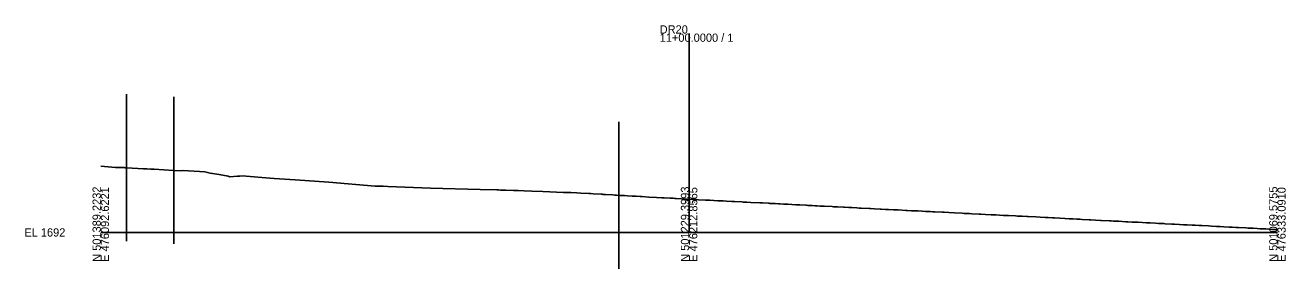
# Model space of a CAD drawing. Extents: x 78027 to 79855, y -93601 to -93005.
# Drawn here: x 79426.8 to 79855.3, y -93589.6 to -93506.7 of the extents above; entities that cross this region are included whole.
import ezdxf

# ---------------------------------------------------------------- set-up
doc = ezdxf.new("R2010")
doc.units = 0
for name, color, linetype in [('Exist Cross Section Cell', 7, 'Continuous'), ('Exist XS Center Line Elevation Label', 7, 'Continuous'), ('Exist XS Ground Line', 7, 'Continuous'), ('Scratch_Level_0', 7, 'Continuous'), ('Scratch_Level_4', 7, 'Continuous'), ('Scratch_Level_5', 7, 'Continuous'), ('Scratch_Level_6', 7, 'Continuous')]:
    doc.layers.add(name, color=color, linetype=linetype)

msp = doc.modelspace()

# ---------------------------------------------------------------- linework, layer by layer
at = {"layer": 'Exist Cross Section Cell'}
for p, q in [((79652.48, -93577.22), (79652.48, -93509.58)), ((79452.48, -93577.22), (79652.48, -93577.22)), ((79652.48, -93577.22), (79852.48, -93577.22))]:
    msp.add_line(p, q, dxfattribs=at)
at = {"layer": 'Exist XS Ground Line'}
msp.add_lwpolyline([(79452.48, -93554.67), (79457.47, -93555.08), (79460.4, -93555.15), (79460.76, -93555.21), (79461.28, -93555.22), (79467, -93555.55), (79468.19, -93555.63), (79469.48, -93555.68), (79470.02, -93555.72), (79470.61, -93555.75), (79477.17, -93556.1), (79479.76, -93556.22), (79480.44, -93556.1), (79487.87, -93556.64), (79489.7, -93557.09), (79492.77, -93557.53), (79495.73, -93558.11), (79496.34, -93558.31), (79498.98, -93558.05), (79499.78, -93558.04), (79501.14, -93557.95), (79501.94, -93558.03), (79509.9, -93558.78), (79511.48, -93558.86), (79518.6, -93559.3), (79529.97, -93560.16), (79545.75, -93561.44), (79548.53, -93561.53), (79550.05, -93561.58), (79564.52, -93562.17), (79581.42, -93562.59), (79587.13, -93562.76), (79587.66, -93562.78), (79588.31, -93562.8), (79589.12, -93562.83), (79590.17, -93562.87), (79592.84, -93562.95), (79594.39, -93563.01), (79596.38, -93563.08), (79599.04, -93563.18), (79602.73, -93563.32), (79609.81, -93563.6), (79612.26, -93563.68), (79614.26, -93563.75), (79615.69, -93563.84), (79618.45, -93563.99), (79619.04, -93564.03), (79619.83, -93564.08), (79622.62, -93564.24), (79622.97, -93564.26), (79623.32, -93564.28), (79624.05, -93564.32), (79626.58, -93564.47), (79627.26, -93564.51), (79627.77, -93564.54), (79629.1, -93564.62), (79630.56, -93564.7), (79631.54, -93564.76), (79633.07, -93564.84), (79633.66, -93564.89), (79634.53, -93564.93), (79635.89, -93565), (79636.36, -93565.03), (79638.81, -93565.17), (79641.37, -93565.31), (79643.26, -93565.41), (79643.67, -93565.43), (79644, -93565.45), (79646.07, -93565.57), (79647.07, -93565.62), (79647.63, -93565.65), (79648.07, -93565.67), (79649.93, -93565.77), (79651.59, -93565.86), (79652.73, -93565.92), (79654.23, -93566), (79655.02, -93566.04), (79655.65, -93566.08), (79658.06, -93566.2), (79659.17, -93566.26), (79659.54, -93566.28), (79660.86, -93566.35), (79662.27, -93566.42), (79664.01, -93566.51), (79665.22, -93566.57), (79666.98, -93566.66), (79667.48, -93566.69), (79667.9, -93566.71), (79670.35, -93566.84), (79670.88, -93566.87), (79672.05, -93566.93), (79673.43, -93567), (79676.48, -93567.16), (79677.41, -93567.2), (79679.64, -93567.32), (79679.97, -93567.34), (79680.31, -93567.35), (79681.79, -93567.43), (79682.84, -93567.48), (79683.35, -93567.51), (79684.54, -93567.57), (79685.36, -93567.62), (79686, -93567.65), (79688.71, -93567.79), (79689.06, -93567.81), (79690.11, -93567.87), (79692.14, -93567.97), (79692.44, -93567.99), (79692.81, -93568.01), (79694.27, -93568.08), (79695.31, -93568.14), (79696.03, -93568.18), (79697, -93568.23), (79697.85, -93568.27), (79698.5, -93568.31), (79701.15, -93568.45), (79701.6, -93568.47), (79702.88, -93568.54), (79704.93, -93568.64), (79705.29, -93568.66), (79706.77, -93568.74), (79707.81, -93568.79), (79709.48, -93568.88), (79710.35, -93568.92), (79711.02, -93568.96), (79713.64, -93569.09), (79714.11, -93569.12), (79715.47, -93569.19), (79717.42, -93569.28), (79717.76, -93569.3), (79719.25, -93569.38), (79720.32, -93569.43), (79721.97, -93569.51), (79722.86, -93569.56), (79723.52, -93569.59), (79726.11, -93569.72), (79726.64, -93569.75), (79728.1, -93569.82), (79729.92, -93569.91), (79730.24, -93569.93), (79731.74, -93570.01), (79732.83, -93570.06), (79733.51, -93570.09), (79734.44, -93570.14), (79735.36, -93570.19), (79736.06, -93570.22), (79738.59, -93570.35), (79739.15, -93570.38), (79740.73, -93570.46), (79742.71, -93570.56), (79745.36, -93570.69), (79746.02, -93570.73), (79746.9, -93570.77), (79747.84, -93570.82), (79748.58, -93570.86), (79751.07, -93570.98), (79751.61, -93571), (79753.28, -93571.09), (79755.18, -93571.19), (79756.76, -93571.27), (79757.96, -93571.33), (79759.4, -93571.41), (79761.03, -93571.49), (79763.47, -93571.61), (79764.08, -93571.64), (79765.67, -93571.73), (79767.34, -93571.81), (79767.75, -93571.83), (79770.4, -93571.97), (79771.82, -93572.04), (79773.47, -93572.13), (79774.57, -93572.19), (79776.04, -93572.26), (79776.73, -93572.3), (79778.54, -93572.39), (79780.17, -93572.48), (79781.73, -93572.56), (79782.91, -93572.62), (79784.33, -93572.69), (79785.32, -93572.74), (79786.09, -93572.78), (79788.43, -93572.9), (79789.1, -93572.94), (79790.65, -93573.03), (79792.37, -93573.11), (79792.68, -93573.13), (79795.36, -93573.27), (79795.99, -93573.3), (79796.81, -93573.35), (79797.82, -93573.4), (79798.59, -93573.44), (79800.96, -93573.56), (79801.67, -93573.6), (79803.13, -93573.68), (79805.11, -93573.77), (79807.98, -93573.93), (79809.24, -93573.99), (79811.01, -93574.08), (79812.07, -93574.14), (79813.42, -93574.21), (79813.91, -93574.23), (79814.27, -93574.25), (79816.56, -93574.37), (79817.53, -93574.42), (79819.24, -93574.51), (79820.52, -93574.58), (79821.76, -93574.64), (79823.52, -93574.73), (79824.56, -93574.79), (79825.93, -93574.86), (79826.41, -93574.88), (79826.78, -93574.9), (79829.06, -93575.02), (79830.04, -93575.07), (79831.73, -93575.16), (79833.03, -93575.23), (79834.24, -93575.29), (79836.03, -93575.39), (79837.05, -93575.44), (79838.39, -93575.51), (79838.91, -93575.54), (79839.3, -93575.56), (79841.75, -93575.69), (79842.48, -93575.73), (79844.24, -93575.82), (79845.55, -93575.89), (79846.67, -93575.95), (79848.56, -93576.05), (79849.57, -93576.1), (79850.84, -93576.17), (79851.78, -93576.22), (79852.48, -93576.26)], dxfattribs=at)
at = {"layer": 'Scratch_Level_0'}
msp.add_lwpolyline([(79452.48, -93554.67), (79457.47, -93555.08), (79460.4, -93555.15), (79460.76, -93555.21), (79461.28, -93555.22), (79467, -93555.55), (79468.19, -93555.63), (79469.48, -93555.68), (79470.02, -93555.72), (79470.61, -93555.75), (79477.17, -93556.1), (79479.76, -93556.22), (79480.44, -93556.1), (79487.87, -93556.64), (79489.7, -93557.09), (79492.77, -93557.53), (79495.73, -93558.11), (79496.34, -93558.31), (79498.98, -93558.05), (79499.78, -93558.04), (79501.14, -93557.95), (79501.94, -93558.03), (79509.9, -93558.78), (79511.48, -93558.86), (79518.6, -93559.3), (79529.97, -93560.16), (79545.75, -93561.44), (79548.53, -93561.53), (79550.05, -93561.58), (79564.52, -93562.17), (79581.42, -93562.59), (79587.13, -93562.76), (79587.66, -93562.78), (79588.31, -93562.8), (79589.12, -93562.83), (79590.17, -93562.87), (79592.84, -93562.95), (79594.39, -93563.01), (79596.38, -93563.08), (79599.04, -93563.18), (79602.73, -93563.32), (79609.81, -93563.6), (79612.26, -93563.68), (79614.26, -93563.75), (79615.69, -93563.84), (79618.45, -93563.99), (79619.04, -93564.03), (79619.83, -93564.08), (79622.62, -93564.24), (79622.97, -93564.26), (79623.32, -93564.28), (79624.05, -93564.32), (79626.58, -93564.47), (79627.26, -93564.51), (79627.77, -93564.54), (79629.1, -93564.62), (79630.56, -93564.7), (79631.54, -93564.76), (79633.07, -93564.84), (79633.66, -93564.89), (79634.53, -93564.93), (79635.89, -93565), (79636.36, -93565.03), (79638.81, -93565.17), (79641.37, -93565.31), (79643.26, -93565.41), (79643.67, -93565.43), (79644, -93565.45), (79646.07, -93565.57), (79647.07, -93565.62), (79647.63, -93565.65), (79648.07, -93565.67), (79649.93, -93565.77), (79651.59, -93565.86), (79652.73, -93565.92), (79654.23, -93566), (79655.02, -93566.04), (79655.65, -93566.08), (79658.06, -93566.2), (79659.17, -93566.26), (79659.54, -93566.28), (79660.86, -93566.35), (79662.27, -93566.42), (79664.01, -93566.51), (79665.22, -93566.57), (79666.98, -93566.66), (79667.48, -93566.69), (79667.9, -93566.71), (79670.35, -93566.84), (79670.88, -93566.87), (79672.05, -93566.93), (79673.43, -93567), (79676.48, -93567.16), (79677.41, -93567.2), (79679.64, -93567.32), (79679.97, -93567.34), (79680.31, -93567.35), (79681.79, -93567.43), (79682.84, -93567.48), (79683.35, -93567.51), (79684.54, -93567.57), (79685.36, -93567.62), (79686, -93567.65), (79688.71, -93567.79), (79689.06, -93567.81), (79690.11, -93567.87), (79692.14, -93567.97), (79692.44, -93567.99), (79692.81, -93568.01), (79694.27, -93568.08), (79695.31, -93568.14), (79696.03, -93568.18), (79697, -93568.23), (79697.85, -93568.27), (79698.5, -93568.31), (79701.15, -93568.45), (79701.6, -93568.47), (79702.88, -93568.54), (79704.93, -93568.64), (79705.29, -93568.66), (79706.77, -93568.74), (79707.81, -93568.79), (79709.48, -93568.88), (79710.35, -93568.92), (79711.02, -93568.96), (79713.64, -93569.09), (79714.11, -93569.12), (79715.47, -93569.19), (79717.42, -93569.28), (79717.76, -93569.3), (79719.25, -93569.38), (79720.32, -93569.43), (79721.97, -93569.51), (79722.86, -93569.56), (79723.52, -93569.59), (79726.11, -93569.72), (79726.64, -93569.75), (79728.1, -93569.82), (79729.92, -93569.91), (79730.24, -93569.93), (79731.74, -93570.01), (79732.83, -93570.06), (79733.51, -93570.09), (79734.44, -93570.14), (79735.36, -93570.19), (79736.06, -93570.22), (79738.59, -93570.35), (79739.15, -93570.38), (79740.73, -93570.46), (79742.71, -93570.56), (79745.36, -93570.69), (79746.02, -93570.73), (79746.9, -93570.77), (79747.84, -93570.82), (79748.58, -93570.86), (79751.07, -93570.98), (79751.61, -93571), (79753.28, -93571.09), (79755.18, -93571.19), (79756.76, -93571.27), (79757.96, -93571.33), (79759.4, -93571.41), (79761.03, -93571.49), (79763.47, -93571.61), (79764.08, -93571.64), (79765.67, -93571.73), (79767.34, -93571.81), (79767.75, -93571.83), (79770.4, -93571.97), (79771.82, -93572.04), (79773.47, -93572.13), (79774.57, -93572.19), (79776.04, -93572.26), (79776.73, -93572.3), (79778.54, -93572.39), (79780.17, -93572.48), (79781.73, -93572.56), (79782.91, -93572.62), (79784.33, -93572.69), (79785.32, -93572.74), (79786.09, -93572.78), (79788.43, -93572.9), (79789.1, -93572.94), (79790.65, -93573.03), (79792.37, -93573.11), (79792.68, -93573.13), (79795.36, -93573.27), (79795.99, -93573.3), (79796.81, -93573.35), (79797.82, -93573.4), (79798.59, -93573.44), (79800.96, -93573.56), (79801.67, -93573.6), (79803.13, -93573.68), (79805.11, -93573.77), (79807.98, -93573.93), (79809.24, -93573.99), (79811.01, -93574.08), (79812.07, -93574.14), (79813.42, -93574.21), (79813.91, -93574.23), (79814.27, -93574.25), (79816.56, -93574.37), (79817.53, -93574.42), (79819.24, -93574.51), (79820.52, -93574.58), (79821.76, -93574.64), (79823.52, -93574.73), (79824.56, -93574.79), (79825.93, -93574.86), (79826.41, -93574.88), (79826.78, -93574.9), (79829.06, -93575.02), (79830.04, -93575.07), (79831.73, -93575.16), (79833.03, -93575.23), (79834.24, -93575.29), (79836.03, -93575.39), (79837.05, -93575.44), (79838.39, -93575.51), (79838.91, -93575.54), (79839.3, -93575.56), (79841.75, -93575.69), (79842.48, -93575.73), (79844.24, -93575.82), (79845.55, -93575.89), (79846.67, -93575.95), (79848.56, -93576.05), (79849.57, -93576.1), (79850.84, -93576.17), (79851.78, -93576.22), (79852.48, -93576.26)], dxfattribs=at)
at = {"layer": 'Scratch_Level_4'}
for p, q in [((79461.28, -93530.22), (79461.28, -93580.22)), ((79477.29, -93531.11), (79477.29, -93581.11)), ((79628.63, -93539.59), (79628.63, -93589.59)), ((79628.63, -93539.59), (79628.63, -93589.59))]:
    msp.add_line(p, q, dxfattribs=at)
at = {"layer": 'Scratch_Level_5'}
msp.add_lwpolyline([(79452.48, -93554.67), (79457.47, -93555.08), (79460.4, -93555.15), (79460.76, -93555.21), (79461.28, -93555.22), (79467, -93555.55), (79468.19, -93555.63), (79469.48, -93555.68), (79470.02, -93555.72), (79470.61, -93555.75), (79477.17, -93556.1), (79479.76, -93556.22), (79480.44, -93556.1), (79487.87, -93556.64), (79489.7, -93557.09), (79492.77, -93557.53), (79495.73, -93558.11), (79496.34, -93558.31), (79498.98, -93558.05), (79499.78, -93558.04), (79501.14, -93557.95), (79501.94, -93558.03), (79509.9, -93558.78), (79511.48, -93558.86), (79518.6, -93559.3), (79529.97, -93560.16), (79545.75, -93561.44), (79548.53, -93561.53), (79550.05, -93561.58), (79564.52, -93562.17), (79581.42, -93562.59), (79587.13, -93562.76), (79587.66, -93562.78), (79588.31, -93562.8), (79589.12, -93562.83), (79590.17, -93562.87), (79592.84, -93562.95), (79594.39, -93563.01), (79596.38, -93563.08), (79599.04, -93563.18), (79602.73, -93563.32), (79609.81, -93563.6), (79612.26, -93563.68), (79614.26, -93563.75), (79615.69, -93563.84), (79618.45, -93563.99), (79619.04, -93564.03), (79619.83, -93564.08), (79622.62, -93564.24), (79622.97, -93564.26), (79623.32, -93564.28), (79624.05, -93564.32), (79626.58, -93564.47), (79627.26, -93564.51), (79627.77, -93564.54), (79629.1, -93564.62), (79630.56, -93564.7), (79631.54, -93564.76), (79633.07, -93564.84), (79633.66, -93564.89), (79634.53, -93564.93), (79635.89, -93565), (79636.36, -93565.03), (79638.81, -93565.17), (79641.37, -93565.31), (79643.26, -93565.41), (79643.67, -93565.43), (79644, -93565.45), (79646.07, -93565.57), (79647.07, -93565.62), (79647.63, -93565.65), (79648.07, -93565.67), (79649.93, -93565.77), (79651.59, -93565.86), (79652.73, -93565.92), (79654.23, -93566), (79655.02, -93566.04), (79655.65, -93566.08), (79658.06, -93566.2), (79659.17, -93566.26), (79659.54, -93566.28), (79660.86, -93566.35), (79662.27, -93566.42), (79664.01, -93566.51), (79665.22, -93566.57), (79666.98, -93566.66), (79667.48, -93566.69), (79667.9, -93566.71), (79670.35, -93566.84), (79670.88, -93566.87), (79672.05, -93566.93), (79673.43, -93567), (79676.48, -93567.16), (79677.41, -93567.2), (79679.64, -93567.32), (79679.97, -93567.34), (79680.31, -93567.35), (79681.79, -93567.43), (79682.84, -93567.48), (79683.35, -93567.51), (79684.54, -93567.57), (79685.36, -93567.62), (79686, -93567.65), (79688.71, -93567.79), (79689.06, -93567.81), (79690.11, -93567.87), (79692.14, -93567.97), (79692.44, -93567.99), (79692.81, -93568.01), (79694.27, -93568.08), (79695.31, -93568.14), (79696.03, -93568.18), (79697, -93568.23), (79697.85, -93568.27), (79698.5, -93568.31), (79701.15, -93568.45), (79701.6, -93568.47), (79702.88, -93568.54), (79704.93, -93568.64), (79705.29, -93568.66), (79706.77, -93568.74), (79707.81, -93568.79), (79709.48, -93568.88), (79710.35, -93568.92), (79711.02, -93568.96), (79713.64, -93569.09), (79714.11, -93569.12), (79715.47, -93569.19), (79717.42, -93569.28), (79717.76, -93569.3), (79719.25, -93569.38), (79720.32, -93569.43), (79721.97, -93569.51), (79722.86, -93569.56), (79723.52, -93569.59), (79726.11, -93569.72), (79726.64, -93569.75), (79728.1, -93569.82), (79729.92, -93569.91), (79730.24, -93569.93), (79731.74, -93570.01), (79732.83, -93570.06), (79733.51, -93570.09), (79734.44, -93570.14), (79735.36, -93570.19), (79736.06, -93570.22), (79738.59, -93570.35), (79739.15, -93570.38), (79740.73, -93570.46), (79742.71, -93570.56), (79745.36, -93570.69), (79746.02, -93570.73), (79746.9, -93570.77), (79747.84, -93570.82), (79748.58, -93570.86), (79751.07, -93570.98), (79751.61, -93571), (79753.28, -93571.09), (79755.18, -93571.19), (79756.76, -93571.27), (79757.96, -93571.33), (79759.4, -93571.41), (79761.03, -93571.49), (79763.47, -93571.61), (79764.08, -93571.64), (79765.67, -93571.73), (79767.34, -93571.81), (79767.75, -93571.83), (79770.4, -93571.97), (79771.82, -93572.04), (79773.47, -93572.13), (79774.57, -93572.19), (79776.04, -93572.26), (79776.73, -93572.3), (79778.54, -93572.39), (79780.17, -93572.48), (79781.73, -93572.56), (79782.91, -93572.62), (79784.33, -93572.69), (79785.32, -93572.74), (79786.09, -93572.78), (79788.43, -93572.9), (79789.1, -93572.94), (79790.65, -93573.03), (79792.37, -93573.11), (79792.68, -93573.13), (79795.36, -93573.27), (79795.99, -93573.3), (79796.81, -93573.35), (79797.82, -93573.4), (79798.59, -93573.44), (79800.96, -93573.56), (79801.67, -93573.6), (79803.13, -93573.68), (79805.11, -93573.77), (79807.98, -93573.93), (79809.24, -93573.99), (79811.01, -93574.08), (79812.07, -93574.14), (79813.42, -93574.21), (79813.91, -93574.23), (79814.27, -93574.25), (79816.56, -93574.37), (79817.53, -93574.42), (79819.24, -93574.51), (79820.52, -93574.58), (79821.76, -93574.64), (79823.52, -93574.73), (79824.56, -93574.79), (79825.93, -93574.86), (79826.41, -93574.88), (79826.78, -93574.9), (79829.06, -93575.02), (79830.04, -93575.07), (79831.73, -93575.16), (79833.03, -93575.23), (79834.24, -93575.29), (79836.03, -93575.39), (79837.05, -93575.44), (79838.39, -93575.51), (79838.91, -93575.54), (79839.3, -93575.56), (79841.75, -93575.69), (79842.48, -93575.73), (79844.24, -93575.82), (79845.55, -93575.89), (79846.67, -93575.95), (79848.56, -93576.05), (79849.57, -93576.1), (79850.84, -93576.17), (79851.78, -93576.22), (79852.48, -93576.26)], dxfattribs=at)
at = {"layer": 'Scratch_Level_6'}
msp.add_lwpolyline([(79452.48, -93554.67), (79457.47, -93555.08), (79460.4, -93555.15), (79460.76, -93555.21), (79461.28, -93555.22), (79467, -93555.55), (79468.19, -93555.63), (79469.48, -93555.68), (79470.02, -93555.72), (79470.61, -93555.75), (79477.17, -93556.1), (79479.76, -93556.22), (79480.44, -93556.1), (79487.87, -93556.64), (79489.7, -93557.09), (79492.77, -93557.53), (79495.73, -93558.11), (79496.34, -93558.31), (79498.98, -93558.05), (79499.78, -93558.04), (79501.14, -93557.95), (79501.94, -93558.03), (79509.9, -93558.78), (79511.48, -93558.86), (79518.6, -93559.3), (79529.97, -93560.16), (79545.75, -93561.44), (79548.53, -93561.53), (79550.05, -93561.58), (79564.52, -93562.17), (79581.42, -93562.59), (79587.13, -93562.76), (79587.66, -93562.78), (79588.31, -93562.8), (79589.12, -93562.83), (79590.17, -93562.87), (79592.84, -93562.95), (79594.39, -93563.01), (79596.38, -93563.08), (79599.04, -93563.18), (79602.73, -93563.32), (79609.81, -93563.6), (79612.26, -93563.68), (79614.26, -93563.75), (79615.69, -93563.84), (79618.45, -93563.99), (79619.04, -93564.03), (79619.83, -93564.08), (79622.62, -93564.24), (79622.97, -93564.26), (79623.32, -93564.28), (79624.05, -93564.32), (79626.58, -93564.47), (79627.26, -93564.51), (79627.77, -93564.54), (79629.1, -93564.62), (79630.56, -93564.7), (79631.54, -93564.76), (79633.07, -93564.84), (79633.66, -93564.89), (79634.53, -93564.93), (79635.89, -93565), (79636.36, -93565.03), (79638.81, -93565.17), (79641.37, -93565.31), (79643.26, -93565.41), (79643.67, -93565.43), (79644, -93565.45), (79646.07, -93565.57), (79647.07, -93565.62), (79647.63, -93565.65), (79648.07, -93565.67), (79649.93, -93565.77), (79651.59, -93565.86), (79652.73, -93565.92), (79654.23, -93566), (79655.02, -93566.04), (79655.65, -93566.08), (79658.06, -93566.2), (79659.17, -93566.26), (79659.54, -93566.28), (79660.86, -93566.35), (79662.27, -93566.42), (79664.01, -93566.51), (79665.22, -93566.57), (79666.98, -93566.66), (79667.48, -93566.69), (79667.9, -93566.71), (79670.35, -93566.84), (79670.88, -93566.87), (79672.05, -93566.93), (79673.43, -93567), (79676.48, -93567.16), (79677.41, -93567.2), (79679.64, -93567.32), (79679.97, -93567.34), (79680.31, -93567.35), (79681.79, -93567.43), (79682.84, -93567.48), (79683.35, -93567.51), (79684.54, -93567.57), (79685.36, -93567.62), (79686, -93567.65), (79688.71, -93567.79), (79689.06, -93567.81), (79690.11, -93567.87), (79692.14, -93567.97), (79692.44, -93567.99), (79692.81, -93568.01), (79694.27, -93568.08), (79695.31, -93568.14), (79696.03, -93568.18), (79697, -93568.23), (79697.85, -93568.27), (79698.5, -93568.31), (79701.15, -93568.45), (79701.6, -93568.47), (79702.88, -93568.54), (79704.93, -93568.64), (79705.29, -93568.66), (79706.77, -93568.74), (79707.81, -93568.79), (79709.48, -93568.88), (79710.35, -93568.92), (79711.02, -93568.96), (79713.64, -93569.09), (79714.11, -93569.12), (79715.47, -93569.19), (79717.42, -93569.28), (79717.76, -93569.3), (79719.25, -93569.38), (79720.32, -93569.43), (79721.97, -93569.51), (79722.86, -93569.56), (79723.52, -93569.59), (79726.11, -93569.72), (79726.64, -93569.75), (79728.1, -93569.82), (79729.92, -93569.91), (79730.24, -93569.93), (79731.74, -93570.01), (79732.83, -93570.06), (79733.51, -93570.09), (79734.44, -93570.14), (79735.36, -93570.19), (79736.06, -93570.22), (79738.59, -93570.35), (79739.15, -93570.38), (79740.73, -93570.46), (79742.71, -93570.56), (79745.36, -93570.69), (79746.02, -93570.73), (79746.9, -93570.77), (79747.84, -93570.82), (79748.58, -93570.86), (79751.07, -93570.98), (79751.61, -93571), (79753.28, -93571.09), (79755.18, -93571.19), (79756.76, -93571.27), (79757.96, -93571.33), (79759.4, -93571.41), (79761.03, -93571.49), (79763.47, -93571.61), (79764.08, -93571.64), (79765.67, -93571.73), (79767.34, -93571.81), (79767.75, -93571.83), (79770.4, -93571.97), (79771.82, -93572.04), (79773.47, -93572.13), (79774.57, -93572.19), (79776.04, -93572.26), (79776.73, -93572.3), (79778.54, -93572.39), (79780.17, -93572.48), (79781.73, -93572.56), (79782.91, -93572.62), (79784.33, -93572.69), (79785.32, -93572.74), (79786.09, -93572.78), (79788.43, -93572.9), (79789.1, -93572.94), (79790.65, -93573.03), (79792.37, -93573.11), (79792.68, -93573.13), (79795.36, -93573.27), (79795.99, -93573.3), (79796.81, -93573.35), (79797.82, -93573.4), (79798.59, -93573.44), (79800.96, -93573.56), (79801.67, -93573.6), (79803.13, -93573.68), (79805.11, -93573.77), (79807.98, -93573.93), (79809.24, -93573.99), (79811.01, -93574.08), (79812.07, -93574.14), (79813.42, -93574.21), (79813.91, -93574.23), (79814.27, -93574.25), (79816.56, -93574.37), (79817.53, -93574.42), (79819.24, -93574.51), (79820.52, -93574.58), (79821.76, -93574.64), (79823.52, -93574.73), (79824.56, -93574.79), (79825.93, -93574.86), (79826.41, -93574.88), (79826.78, -93574.9), (79829.06, -93575.02), (79830.04, -93575.07), (79831.73, -93575.16), (79833.03, -93575.23), (79834.24, -93575.29), (79836.03, -93575.39), (79837.05, -93575.44), (79838.39, -93575.51), (79838.91, -93575.54), (79839.3, -93575.56), (79841.75, -93575.69), (79842.48, -93575.73), (79844.24, -93575.82), (79845.55, -93575.89), (79846.67, -93575.95), (79848.56, -93576.05), (79849.57, -93576.1), (79850.84, -93576.17), (79851.78, -93576.22), (79852.48, -93576.26)], dxfattribs=at)

# ---------------------------------------------------------------- texts
at = {"layer": 'Exist Cross Section Cell'}
for s, p in [('11+00.0000 / 1', (79642.48, -93512.38)), ('DR20', (79642.48, -93509.58)), ('EL 1692', (79426.48, -93578.62))]:
    msp.add_text(s, height=2.8, dxfattribs=at).set_placement(p)
for s, p in [('N 501389.2232', (79452.48, -93587.22)), ('E 476092.6221', (79455.28, -93587.22)), ('N 501229.3993', (79652.48, -93587.22)), ('E 476212.8565', (79655.28, -93587.22)), ('N 501069.5755', (79852.48, -93587.22)), ('E 476333.0910', (79855.28, -93587.22))]:
    msp.add_text(s, height=2.8, rotation=90, dxfattribs=at).set_placement(p)
at = {"layer": 'Exist XS Center Line Elevation Label'}
msp.add_text('1703.31', height=0.75, dxfattribs=at).set_placement((79650.85, -93567.16))

doc.saveas('drawing.dxf')
